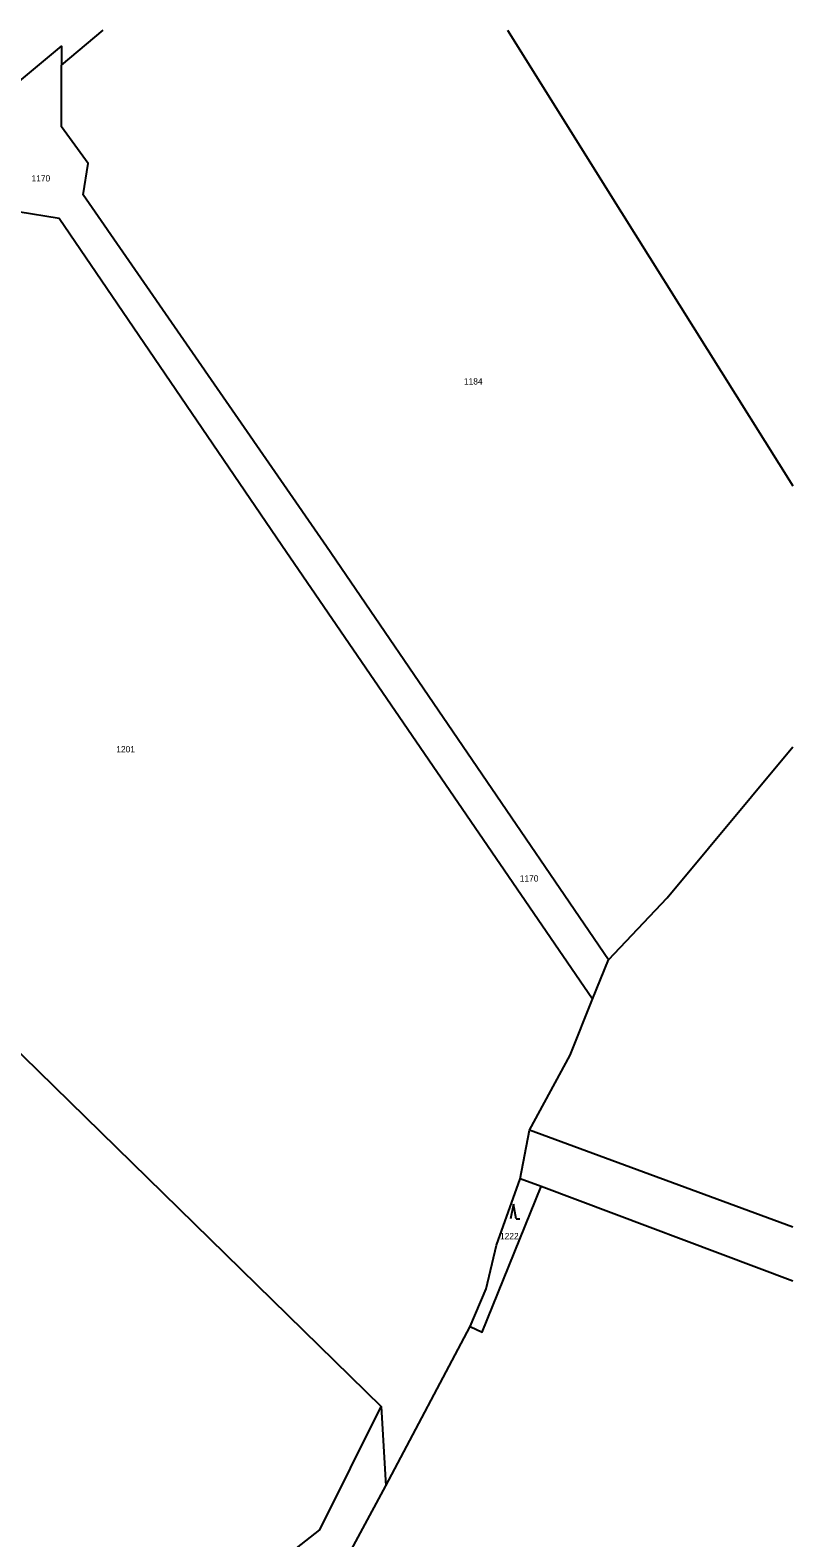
# Model space of a CAD drawing. Extents: x -520431 to -517205, y -1075927 to -1074013.
# Drawn here: x -517411.8 to -517205.1, y -1074423.3 to -1074014.8 of the extents above; entities that cross this region are included whole.
import ezdxf

# ---------------------------------------------------------------- set-up
doc = ezdxf.new("R2010")
doc.units = 0
for name, color, linetype in [('Hranice parcel', 7, 'Continuous'), ('Parcelní čísla', 7, 'Continuous'), ('Značky kultur', 7, 'Continuous')]:
    doc.layers.add(name, color=color, linetype=linetype)

msp = doc.modelspace()

# ---------------------------------------------------------------- linework, layer by layer
at = {"layer": 'Hranice parcel'}
for p, q in [((-517259.37, -1074277.35), (-517255.06, -1074266.65)), ((-517278.96, -1074325.99), (-517276.45, -1074312.77)), ((-517273.29, -1074328.11), (-517278.96, -1074325.99)), ((-517315.39, -1074409.18), (-517292.5, -1074366.04)), ((-517316.62, -1074387.64), (-517315.39, -1074409.18))]:
    msp.add_line(p, q, dxfattribs=at)
for points in [[(-517403.28, -1074024.27), (-517391.94, -1074014.78)], [(-517282.44, -1074014.78), (-517251.49, -1074064.17), (-517205.09, -1074138.2)], [(-517437.36, -1074055.27), (-517445.5, -1074054.27), (-517403.27, -1074019.12), (-517403.28, -1074024.27)], [(-517255.06, -1074266.65), (-517331.43, -1074154.72), (-517397.36, -1074059.42), (-517396.03, -1074050.95), (-517403.3, -1074040.98), (-517403.28, -1074024.27)], [(-517259.37, -1074277.35), (-517343.54, -1074154.39), (-517403.87, -1074065.85), (-517415.04, -1074064.04), (-517419.79, -1074057.44), (-517437.36, -1074055.27)], [(-517536.38, -1074173.02), (-517426.5, -1074280.32), (-517316.62, -1074387.64)], [(-517255.06, -1074266.65), (-517239.13, -1074249.82), (-517205.09, -1074208.98)], [(-517276.45, -1074312.77), (-517265.47, -1074292.5), (-517259.37, -1074277.35)], [(-517205.09, -1074339.1), (-517276.45, -1074312.77)], [(-517292.5, -1074366.04), (-517288.18, -1074355.8), (-517285.39, -1074343.98), (-517278.96, -1074325.99)], [(-517292.5, -1074366.04), (-517289.28, -1074367.51), (-517273.29, -1074328.11)], [(-517205.09, -1074353.69), (-517273.29, -1074328.11)], [(-517416.21, -1074485.37), (-517437.62, -1074476.96), (-517441.67, -1074462.71), (-517420.36, -1074450.79), (-517353.92, -1074437.38), (-517333.23, -1074421.09), (-517316.62, -1074387.64)], [(-517383.44, -1074547.78), (-517382.28, -1074541.08), (-517374.46, -1074522.04), (-517354.05, -1074480.84), (-517315.39, -1074409.18)]]:
    msp.add_lwpolyline(points, dxfattribs=at)
at = {"layer": 'Značky kultur'}
for p, q in [((-517280.81, -1074332.81), (-517281.56, -1074336.81)), ((-517280.06, -1074336.81), (-517280.81, -1074332.81)), ((-517280.06, -1074336.81), (-517279.06, -1074336.81))]:
    msp.add_line(p, q, dxfattribs=at)

# ---------------------------------------------------------------- texts
at = {"layer": 'Parcelní čísla'}
for s, p in [('1170', (-517411.37, -1074055.78)), ('1184', (-517294.22, -1074110.79)), ('1201', (-517388.41, -1074210.45)), ('1170', (-517279.09, -1074245.45)), ('1222', (-517284.44, -1074342.34))]:
    msp.add_text(s, height=1.7, dxfattribs=at).set_placement(p)

doc.saveas('drawing.dxf')
